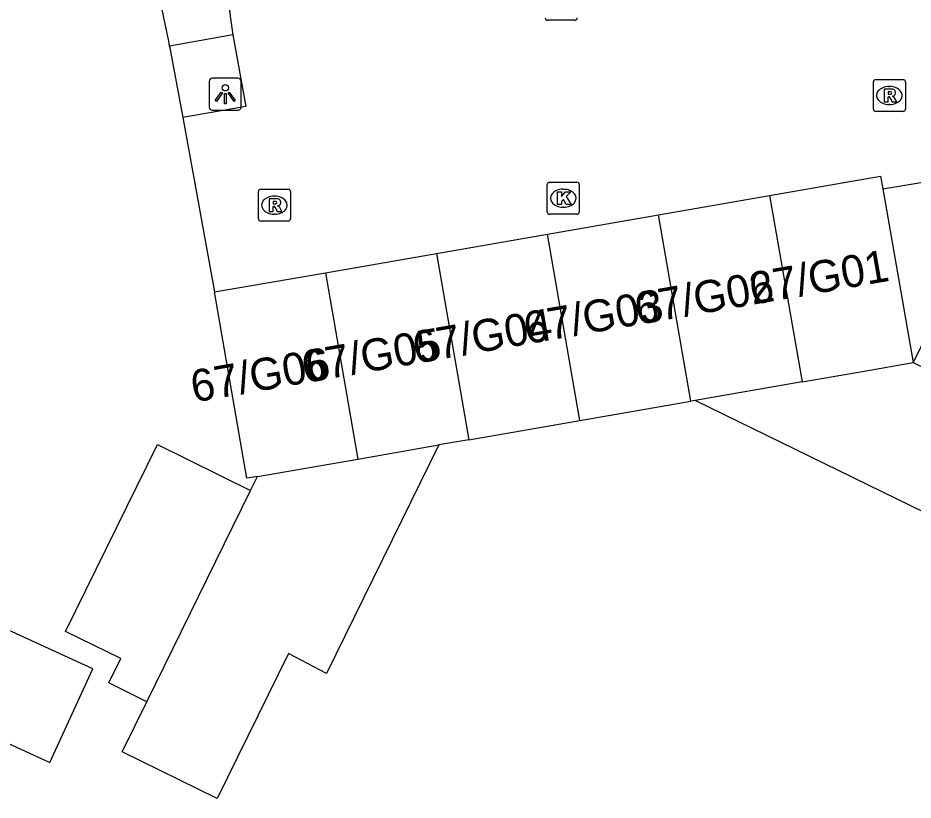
# Model space of a CAD drawing. Extents: x 162880 to 165536, y 384011 to 385179.
# Drawn here: x 163957.33 to 163985.31, y 384540.3 to 384564.74 of the extents above; entities that cross this region are included whole.
import ezdxf

# ---------------------------------------------------------------- set-up
doc = ezdxf.new("R2010")
doc.units = 0
for name, color, linetype in [('IMGEO_Groenvoorziening', 7, 'Continuous'), ('IMGEO_Kolk', 7, 'Continuous'), ('IMGEO_Lichtpunt', 7, 'Continuous'), ('IMGEO_Pand', 7, 'Continuous'), ('IMGEO_Pand_nummerreeks', 7, 'Continuous'), ('IMGEO_Rijbaan_lokaal_open', 7, 'Continuous'), ('IMGEO_Rioolput', 7, 'Continuous'), ('IMGEO_Voetpad_open', 7, 'Continuous')]:
    doc.layers.add(name, color=color, linetype=linetype)

msp = doc.modelspace()

# ---------------------------------------------------------------- linework, layer by layer
at = {"layer": 'IMGEO_Groenvoorziening'}
msp.add_lwpolyline([(163962.07, 384563.86), (163962.484, 384561.624)], dxfattribs=at)
at = {"layer": 'IMGEO_Kolk'}
for p, q in [((163974.736, 384564.666), (163973.884, 384564.666)), ((163973.871, 384558.68), (163973.871, 384559.532)), ((163973.946, 384559.606), (163974.798, 384559.606)), ((163974.872, 384559.532), (163974.872, 384558.68)), ((163974.359, 384559.386), (163974.384, 384559.386)), ((163974.382, 384558.826), (163974.357, 384558.826)), ((163974.798, 384558.606), (163973.946, 384558.606))]:
    msp.add_line(p, q, dxfattribs=at)
for points in [[(163974.736, 384564.666), (163973.884, 384564.666)], [(163973.871, 384558.68), (163973.871, 384559.532)], [(163973.946, 384559.606), (163974.798, 384559.606)], [(163974.872, 384559.532), (163974.872, 384558.68)], [(163974.192, 384559.306), (163974.315, 384559.306), (163974.315, 384559.155), (163974.445, 384559.306), (163974.609, 384559.306), (163974.463, 384559.155), (163974.616, 384558.906), (163974.464, 384558.906), (163974.379, 384559.07), (163974.315, 384559.003), (163974.315, 384558.906), (163974.192, 384558.906), (163974.192, 384559.306)], [(163974.798, 384558.606), (163973.946, 384558.606)]]:
    msp.add_lwpolyline(points, dxfattribs=at)
for centre, start, end in [((163973.886, 384564.742), 181.552, 268.448), ((163973.886, 384564.742), 181.552, 268.448), ((163974.734, 384564.742), 271.552, 358.448), ((163974.734, 384564.742), 271.552, 358.448), ((163973.948, 384559.53), 91.552, 178.448), ((163973.948, 384559.53), 91.552, 178.448), ((163974.796, 384559.53), 1.552, 88.448), ((163974.796, 384559.53), 1.552, 88.448), ((163973.948, 384558.682), 181.552, 268.448), ((163973.948, 384558.682), 181.552, 268.448), ((163974.796, 384558.682), 271.552, 358.448), ((163974.796, 384558.682), 271.552, 358.448)]:
    msp.add_arc(centre, 0.0765, start, end, dxfattribs=at)
for centre, major_axis, ratio, start_param, end_param in [((163974.358, 384559.106), (-0.387, 0.002), 0.722429, 4.712389, 7.853982), ((163974.383, 384559.106), (-0.39, 0.002), 0.717154, 1.570796, 4.712389)]:
    msp.add_ellipse(centre, major_axis=major_axis, ratio=ratio, start_param=start_param, end_param=end_param, dxfattribs=at)
at = {"layer": 'IMGEO_Lichtpunt'}
for p, q in [((163964.213, 384562.853), (163963.405, 384562.853)), ((163964.213, 384562.853), (163963.405, 384562.853)), ((163963.311, 384562.758), (163963.311, 384561.951)), ((163963.311, 384562.758), (163963.311, 384561.951)), ((163964.307, 384561.951), (163964.307, 384562.758)), ((163964.307, 384561.951), (163964.307, 384562.758)), ((163963.405, 384561.857), (163964.213, 384561.857)), ((163963.405, 384561.857), (163964.213, 384561.857))]:
    msp.add_line(p, q, dxfattribs=at)
for points in [[(163963.685, 384562.422), (163963.724, 384562.394), (163963.536, 384562.132), (163963.498, 384562.159), (163963.685, 384562.422)], [(163963.787, 384562.374), (163963.834, 384562.374), (163963.834, 384562.052), (163963.787, 384562.052), (163963.787, 384562.374)], [(163963.897, 384562.394), (163963.935, 384562.421), (163964.122, 384562.159), (163964.083, 384562.131), (163963.897, 384562.394)]]:
    msp.add_lwpolyline(points, dxfattribs=at)
msp.add_circle((163963.81, 384562.556), 0.0994, dxfattribs=at)
for centre, start, end in [((163963.405, 384562.758), 90, 180), ((163963.405, 384562.758), 90, 180), ((163964.213, 384562.758), 0, 90), ((163964.213, 384562.758), 0, 90), ((163963.405, 384561.951), 180, 270), ((163963.405, 384561.951), 180, 270), ((163964.213, 384561.951), 270, 0), ((163964.213, 384561.951), 270, 360)]:
    msp.add_arc(centre, 0.0946, start, end, dxfattribs=at)
at = {"layer": 'IMGEO_Pand'}
for points in [[(163980.822, 384559.189), (163984.292, 384559.792), (163984.361, 384559.396)], [(163984.361, 384559.396), (163985.304, 384553.97)], [(163977.353, 384558.587), (163980.822, 384559.189)], [(163980.822, 384559.189), (163981.834, 384553.367)], [(163973.883, 384557.984), (163977.353, 384558.587)], [(163978.364, 384552.765), (163977.353, 384558.587)], [(163970.413, 384557.381), (163973.883, 384557.984)], [(163974.894, 384552.162), (163973.883, 384557.984)], [(163966.944, 384556.779), (163970.413, 384557.381)], [(163970.413, 384557.381), (163971.425, 384551.559)], [(163963.474, 384556.176), (163966.944, 384556.779)], [(163966.944, 384556.779), (163967.955, 384550.956)], [(163964.815, 384550.411), (163964.486, 384550.354), (163964.33, 384551.25), (163963.474, 384556.176)], [(163981.834, 384553.367), (163983.773, 384553.704), (163985.304, 384553.97)], [(163985.304, 384553.97), (163988.359, 384552.478)], [(163981.834, 384553.367), (163978.499, 384552.788)], [(163978.499, 384552.788), (163978.364, 384552.765)], [(163986.582, 384548.84), (163978.499, 384552.788)], [(163974.894, 384552.162), (163978.364, 384552.765)], [(163971.425, 384551.559), (163974.894, 384552.162)], [(163961.36, 384543.372), (163960.166, 384543.958), (163960.541, 384544.723), (163958.821, 384545.567), (163961.687, 384551.405), (163964.601, 384549.975)], [(163970.485, 384551.396), (163966.977, 384544.25), (163965.784, 384544.875), (163963.561, 384540.345), (163960.59, 384541.804), (163961.36, 384543.372)], [(163967.955, 384550.956), (163970.485, 384551.396)], [(163971.425, 384551.559), (163970.485, 384551.396)], [(163964.815, 384550.411), (163967.955, 384550.956)], [(163964.601, 384549.975), (163964.815, 384550.411)], [(163961.36, 384543.372), (163964.601, 384549.975)], [(163955.593, 384542.722), (163958.329, 384541.473), (163959.668, 384544.405), (163955.123, 384546.481), (163954.339, 384544.764), (163950.974, 384546.301), (163948.817, 384541.571), (163946.741, 384537.021), (163949.319, 384535.845), (163948.962, 384535.063), (163950.922, 384534.169), (163951.292, 384534.978), (163951.901, 384534.7), (163953.977, 384539.249), (163955.593, 384542.722)]]:
    msp.add_lwpolyline(points, dxfattribs=at)
at = {"layer": 'IMGEO_Rijbaan_lokaal_open'}
for points in [[(163963.88, 384565.396), (163964.05, 384564.206)], [(163964.05, 384564.206), (163964.452, 384561.974), (163962.484, 384561.624)], [(163962.484, 384561.624), (163963.474, 384556.176)], [(163984.361, 384559.396), (163988.286, 384560.057)]]:
    msp.add_lwpolyline(points, dxfattribs=at)
at = {"layer": 'IMGEO_Rioolput'}
for p, q in [((163984.064, 384561.889), (163984.064, 384562.741)), ((163984.139, 384562.815), (163984.991, 384562.815)), ((163984.552, 384562.595), (163984.577, 384562.595)), ((163985.065, 384562.741), (163985.065, 384561.889)), ((163984.575, 384562.035), (163984.55, 384562.035)), ((163984.991, 384561.815), (163984.139, 384561.815)), ((163964.846, 384558.462), (163964.846, 384559.314)), ((163964.921, 384559.388), (163965.773, 384559.388)), ((163965.847, 384559.314), (163965.847, 384558.462)), ((163965.334, 384559.168), (163965.359, 384559.168)), ((163965.773, 384558.388), (163964.921, 384558.388)), ((163965.357, 384558.608), (163965.332, 384558.608))]:
    msp.add_line(p, q, dxfattribs=at)
for points in [[(163984.064, 384561.889), (163984.064, 384562.741)], [(163984.139, 384562.815), (163984.991, 384562.815)], [(163985.065, 384562.741), (163985.065, 384561.889)], [(163984.653, 384562.513), (163984.401, 384562.515), (163984.401, 384562.115)], [(163984.579, 384562.434), (163984.525, 384562.434), (163984.525, 384562.353)], [(163984.525, 384562.353), (163984.577, 384562.353)], [(163984.401, 384562.115), (163984.525, 384562.115), (163984.525, 384562.277), (163984.536, 384562.277)], [(163984.583, 384562.248), (163984.654, 384562.115), (163984.794, 384562.115), (163984.729, 384562.241)], [(163984.991, 384561.815), (163984.139, 384561.815)], [(163964.846, 384558.462), (163964.846, 384559.314)], [(163964.921, 384559.388), (163965.773, 384559.388)], [(163965.847, 384559.314), (163965.847, 384558.462)], [(163965.435, 384559.086), (163965.183, 384559.088), (163965.183, 384558.688)], [(163965.361, 384559.007), (163965.307, 384559.007), (163965.307, 384558.926)], [(163965.183, 384558.688), (163965.307, 384558.688), (163965.307, 384558.85), (163965.318, 384558.85)], [(163965.307, 384558.926), (163965.359, 384558.926)], [(163965.365, 384558.821), (163965.436, 384558.688), (163965.576, 384558.688), (163965.511, 384558.814)], [(163965.773, 384558.388), (163964.921, 384558.388)]]:
    msp.add_lwpolyline(points, dxfattribs=at)
for centre, radius, start, end in [((163984.141, 384562.739), 0.0765, 91.552, 178.448), ((163984.141, 384562.739), 0.0765, 91.552, 178.448), ((163984.989, 384562.739), 0.0765, 1.552, 88.448), ((163984.989, 384562.739), 0.0765, 1.552, 88.448), ((163984.561, 384562.542), 0.19, 274.7715, 282.9687), ((163984.585, 384562.338), 0.0964, 77.0061, 93.1865), ((163984.599, 384562.395), 0.0378, 276.6634, 79.6772), ((163984.652, 384562.403), 0.109, 350.3612, 89.416), ((163984.65, 384562.403), 0.112, 277.5842, 350.9817), ((163984.634, 384562.188), 0.108, 29.5134, 73.7905), ((163984.535, 384562.224), 0.0533, 26.0293, 88.6989), ((163984.141, 384561.891), 0.0765, 181.552, 268.448), ((163984.141, 384561.891), 0.0765, 181.552, 268.448), ((163984.989, 384561.891), 0.0765, 271.552, 358.448), ((163984.989, 384561.891), 0.0765, 271.552, 358.448), ((163964.923, 384559.312), 0.0765, 91.552, 178.448), ((163964.923, 384559.312), 0.0765, 91.552, 178.448), ((163965.771, 384559.312), 0.0765, 1.552, 88.448), ((163965.771, 384559.312), 0.0765, 1.552, 88.448), ((163965.367, 384558.911), 0.0964, 77.0061, 93.1865), ((163965.381, 384558.968), 0.0378, 276.6634, 79.6772), ((163965.434, 384558.976), 0.109, 350.3612, 89.416), ((163965.432, 384558.976), 0.112, 277.5842, 350.9817), ((163965.317, 384558.797), 0.0533, 26.0293, 88.6989), ((163965.343, 384559.115), 0.19, 274.7715, 282.9687), ((163965.416, 384558.761), 0.108, 29.5134, 73.7905), ((163964.923, 384558.464), 0.0765, 181.552, 268.448), ((163964.923, 384558.464), 0.0765, 181.552, 268.448), ((163965.771, 384558.464), 0.0765, 271.552, 358.448), ((163965.771, 384558.464), 0.0765, 271.552, 358.448)]:
    msp.add_arc(centre, radius, start, end, dxfattribs=at)
for centre, major_axis, ratio, start_param, end_param in [((163984.551, 384562.315), (-0.387, 0.002), 0.722429, 4.712389, 7.853982), ((163984.576, 384562.315), (-0.39, 0.002), 0.717154, 1.570796, 4.712389), ((163965.333, 384558.888), (-0.387, 0.002), 0.722429, 4.712389, 7.853982), ((163965.358, 384558.888), (-0.39, 0.002), 0.717154, 1.570796, 4.712389)]:
    msp.add_ellipse(centre, major_axis=major_axis, ratio=ratio, start_param=start_param, end_param=end_param, dxfattribs=at)
at = {"layer": 'IMGEO_Voetpad_open'}
for points in [[(163962.07, 384563.86), (163962.042, 384564.009), (163961.817, 384565.095), (163963.88, 384565.396)], [(163964.05, 384564.206), (163962.07, 384563.86)], [(163988.286, 384560.057), (163985.304, 384553.97)]]:
    msp.add_lwpolyline(points, dxfattribs=at)

# ---------------------------------------------------------------- texts
at = {"layer": 'IMGEO_Pand_nummerreeks'}
for s, p in [('67/G01', (163980.284, 384555.774)), ('67/G02', (163976.699, 384555.147)), ('67/G03', (163973.235, 384554.541)), ('67/G04', (163969.765, 384553.934)), ('67/G05', (163966.295, 384553.327)), ('67/G06', (163962.825, 384552.72))]:
    msp.add_text(s, height=1, rotation=9.9208, dxfattribs=at).set_placement(p)

doc.saveas('drawing.dxf')
